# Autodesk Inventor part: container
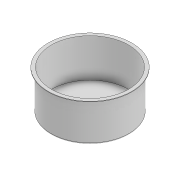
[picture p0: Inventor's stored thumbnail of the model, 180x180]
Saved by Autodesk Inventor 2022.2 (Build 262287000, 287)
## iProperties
Created: 2022-03
Part Number: container
Material: Generic
Document SubType Name: Modeling
Designer: OHIL G H
Density: 1 g/cm^3
Appearance: Default
Author: OHIL G H
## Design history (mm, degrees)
sketch "Sketch1"
  geometry: C1 r 70 at (0, 0); 1 further point
  constraints: 1 centre point, 1 coincident
  dimensions: "d0" = 140 diameter of C1
extrude "Extrusion1" new body sketch "Sketch1" distance "d1" = 70; taper "d2" = 0 deg
sketch "Sketch2"
  geometry: C1 r 69 at (0, 0); 1 further point
  constraints: 1 centre point, 1 coincident
  dimensions: "d3" = 138 diameter of C1
extrude "Extrusion2" cut sketch "Sketch2" distance "d4" = 68; taper "d5" = 0 deg
sketch "Sketch3"
  geometry: C1 r 75 at (0, 0); C2 r 69 at (0, 0); 1 further point
  constraints: 2 centre point, 2 coincident
  dimensions: "d6" = 150 diameter of C1
extrude "Extrusion3" join sketch "Sketch3" distance "d7" = 1; taper "d8" = 0 deg
fillet "Fillet1" dims "d9" = 3
body "Solid1"
